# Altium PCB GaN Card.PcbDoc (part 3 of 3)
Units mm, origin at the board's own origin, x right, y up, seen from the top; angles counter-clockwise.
Board outline 50 x 40 mm, 6 copper layers (Top Layer, MidLayer1, MidLayer2, MidLayer3, MidLayer4, Bottom Layer), stack 1.981 mm thick; 88 components, 77 nets, 322 pads, 257 vias.
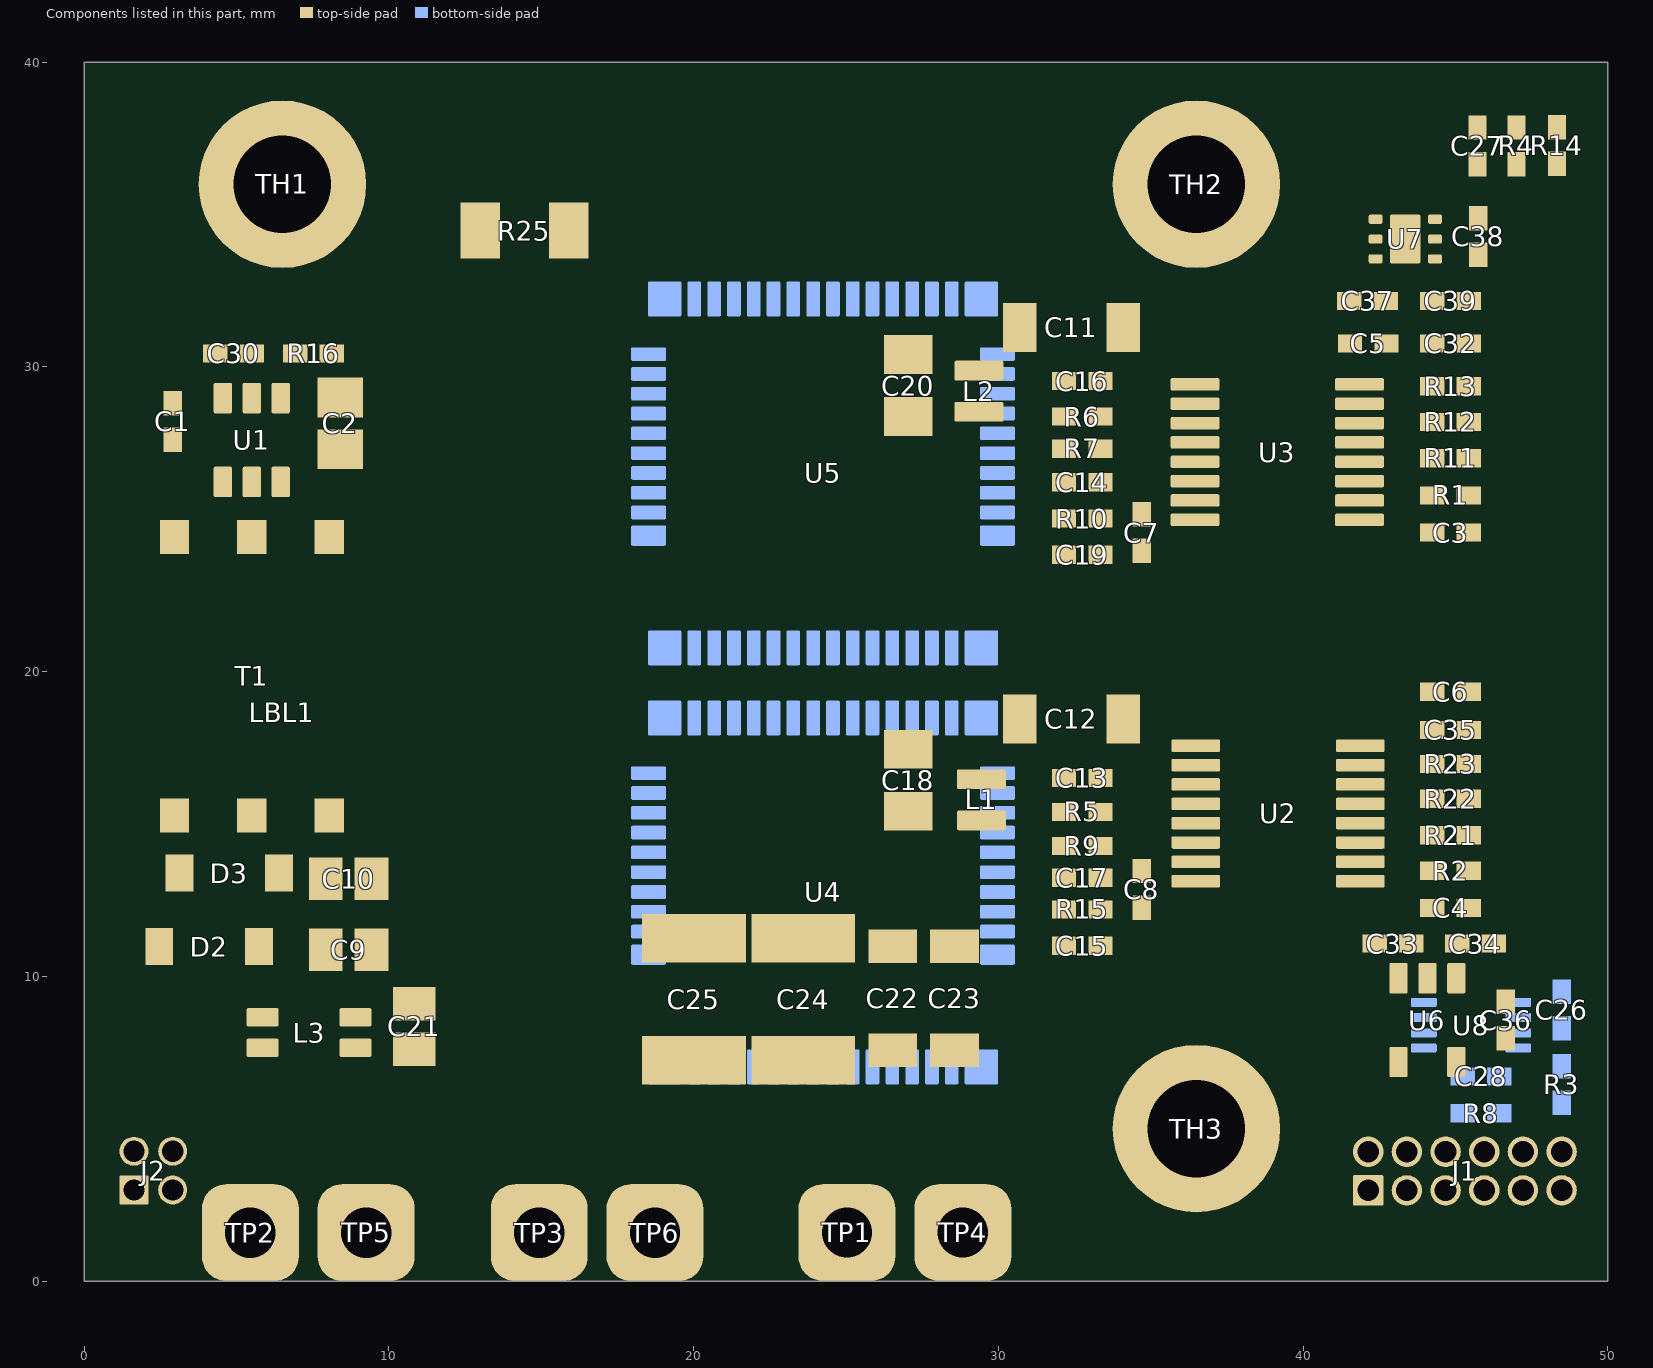
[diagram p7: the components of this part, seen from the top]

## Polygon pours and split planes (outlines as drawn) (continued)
SW on MidLayer2 "MidLayer1-SW" (solid, pour order 532): 29.353,18.554 29.268,18.639 29.268,21.012 30.406,22.15 36.288,22.15 36.844,21.593 37.454,20.984 37.454,11.342 36.326,10.214 28.411,10.214 27.421,11.205 27.421,16.547
PGND on MidLayer2 "MIDLAYER2_PGND_P528" (solid, pour order 528): 21.194,10.428 21.096,10.526 21.096,11.6 21.321,11.825 21.352,11.794 25.929,11.794 26.096,11.628 26.096,10.504 26.02,10.428
PGND on MidLayer2 "MIDLAYER2_PGND_P511" (solid, remove dead copper, pour order 511): 11.995,25.558 8.687,22.25 2.35,22.25 0.56,20.46 0.56,5.761 1.321,5 3.229,5 3.66,4.569 3.66,0.463 4.123,0 11.611,0 11.85,0.239 11.85,15.877 19.073,23.1 25.7,23.1 26.595,23.995 26.595,33.294 25.588,34.3 16.181,34.301 11.995,30.114
SW on MidLayer2 "MidLayer3-SW 1" (solid, pour order 518): 20.657,12.81 25.89,12.81 26.786,13.707 26.786,17.493 27.101,17.712 28.415,19.026 28.415,21.525 27.581,22.25 19.129,22.25 12.76,15.881 12.76,0.23 19.805,0.23 19.805,11.958
PGND on MidLayer2 "MidLayer1-PGND" (solid, pour order 513): 27.421,32.396 28.675,33.65 35.798,33.65 37.454,31.994 37.454,24.574 36.43,23.55 29.909,23.55 27.421,26.038
5V0 on MidLayer2 "MidLayer2-5V0" (solid, remove dead copper, pour order 502): 15.538,35.326 10.199,29.987 10.212,26.377 7.637,23.803 3.132,23.803 0.56,26.336 0.56,38.61 1.65,39.7 49.2,39.7 50,38.9 50,0.5 40.4,0.5 40.4,32.053 37.126,35.326
HVBUS on MidLayer2 "MidLayer4-PGND" (solid, pour order 469): 20.32,7.914 20.588,8.182 20.603,8.182 30.324,8.182 30.764,7.742 30.764,0.234 24.176,0.234 20.32,4.09
PGND on MidLayer1 "MidLayer1-PGND" (solid, pour order 418): 27.421,32.396 28.675,33.65 35.798,33.65 37.454,31.994 37.454,24.574 36.43,23.55 28.97,23.55 27.421,25.099
DGND on MidLayer1 "MidLayer1-DGND" (solid, remove dead copper, pour order 503): 49.754,39.153 49.2,39.707 1.65,39.7 0.56,38.61 0.56,26.336 3.132,23.803 7.637,23.803 10.208,26.374 10.208,29.995 15.538,35.326 35.842,35.326 37.126,35.326 40.4,32.053 40.4,0.246 49.754,0.246
PGND on MidLayer1 "MIDLAYER1_PGND_P519" (solid, remove dead copper, pour order 519): 11.995,25.558 8.687,22.25 2.35,22.25 0.56,20.46 0.56,5.761 1.321,5 3.229,5 3.66,4.569 3.66,0.463 4.123,0 11.611,0 11.85,0.239 11.85,16.018 18.932,23.1 25.7,23.1 26.595,23.995 26.595,33.294 25.588,34.3 16.181,34.301 11.995,30.114
HVBUS on MidLayer1 "MidLayer4-PGND" (solid, pour order 468): 19.997,7.591 20.588,8.182 20.603,8.182 30.324,8.182 30.764,7.742 30.764,0.246 24.164,0.246 19.997,4.413
PGND on MidLayer1 "MIDLAYER1_PGND_P526" (solid, pour order 526): 21.194,10.428 21.096,10.526 21.096,11.6 21.321,11.825 21.352,11.794 25.929,11.794 26.096,11.628 26.096,10.504 26.02,10.428
SW on MidLayer1 "MidLayer3-SW 1" (solid, pour order 520): 20.657,12.81 25.89,12.81 26.786,13.707 26.786,17.493 27.101,17.712 28.415,19.026 28.415,21.525 27.581,22.25 19.129,22.25 12.76,15.881 12.76,0.23 19.805,0.23 19.805,11.958
SW on MidLayer1 "MidLayer1-SW" (solid, pour order 420): 29.353,18.554 29.268,18.639 29.268,21.012 30.406,22.15 36.288,22.15 36.844,21.593 37.454,20.984 37.454,11.342 36.326,10.214 28.411,10.214 27.421,11.205 27.421,16.547
SW on MidLayer3 "MIDLAYER3_SW_P539" (solid, pour order 539): 19.431,16.798 25.003,16.798 25.003,19.001 25.682,19.679 27.845,19.679 28.31,20.144 28.31,21.637 27.951,21.995 19.782,21.995 19.377,21.591
SW on MidLayer3 "MidLayer1-SW" (solid, pour order 533): 29.268,18.466 29.268,21.012 30.406,22.15 36.288,22.15 36.844,21.593 37.454,20.984 37.454,11.342 36.326,10.214 28.411,10.214 27.421,11.205 27.421,16.547
PGND on MidLayer3 "MIDLAYER3_PGND_P530" (solid, pour order 530): 21.194,10.428 21.096,10.526 21.096,11.6 21.321,11.825 21.352,11.794 25.929,11.794 26.096,11.628 26.096,10.504 26.02,10.428
SW on MidLayer3 "MidLayer3-SW 1" (solid, pour order 522): 19.805,11.958 19.805,15.32 19.501,15.624 16.411,15.624 12.76,12.023 12.76,0.23 19.805,0.23
PGND on MidLayer3 "MIDLAYER3_PGND_P521" (solid, pour order 521): 15.249,16.158 19.874,16.158 20.379,15.653 20.379,11.157 21.004,10.532 26.05,10.532 26.595,11.077 26.595,24.493 26.595,32.38 25.191,33.784 16.234,33.784 11.995,29.545 11.995,25.558 8.687,22.25 2.35,22.25 0.56,20.46 0.56,5.761 1.321,5 3.229,5 3.66,4.569 3.66,0.463 4.123,0 11.611,0 11.995,0.384 11.995,12.904
PGND on MidLayer3 "MidLayer1-PGND" (solid, remove dead copper, pour order 515): 27.421,32.396 28.675,33.65 35.798,33.65 37.454,31.994 37.454,24.574 36.43,23.55 28.995,23.55 27.421,25.125
3V3 on MidLayer3 "MidLayer3-3V3" (solid, pour order 505): 15.538,35.326 10.199,29.987 10.212,26.377 7.637,23.803 4.053,23.803 0.56,27.243 0.56,38.61 1.65,39.7 49.2,39.7 50,38.9 50,0.5 40.4,0.5 40.4,32.053 37.126,35.326
HVBUS on MidLayer3 "MidLayer4-PGND" (solid, pour order 470): 20.32,7.914 20.588,8.182 30.324,8.182 30.764,7.742 30.764,0.234 24.176,0.234 20.32,4.09

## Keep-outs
Keep-Out Layer:
  lines w0.178: 32,-0.006 32.006,0 ; 45,40 0,40 0,0 19,0 30,-0.006 50,0 50,40
  text ".Layer_Name" at -16.126,-55.229 h0.6

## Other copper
Top Layer:
  pour cut-out: 46.209,34.237 46.277,34.305 46.277,35.503 45.236,35.503 45.241,35.498 45.241,34.3 45.457,34.084
  pour cut-out: 45.274,38.412 48.787,38.412 48.787,37.222 48.787,36.118 46.563,36.118 46.553,36.108 46.543,36.118 45.141,36.118 45.141,38.279
  region net NetC20_1: 28.526,31.042 28.686,31.203 28.686,31.364 28.5,31.55 26.58,31.55 26.24,31.209 26.24,30.02 27.84,30.407 27.84,30.862 28.02,31.042

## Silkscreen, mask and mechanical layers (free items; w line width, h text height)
Top Overlay:
  lines w0.254: 29.493,20.247 29.493,20.755
  text "GaN Card" at 17.989,36.759 h1.52
  text "PMP41126B" at 17.9,33.94 h1.52
  text "SW" at 16.112,3.982 h0.71
  text "HV-" at 6.917,3.909 h0.71
  text "HV+" at 25.868,3.909 h0.71
  text ".Layer_Name" at -16.126,-55.229 h0.6
Bottom Overlay:
  text "not FCC approved for resale." at 31.63,34.295 h0.71
  text ".Layer_Name" at -16.126,-55.229 h0.6
Top Paste:
  text ".Layer_Name" at -16.126,-55.229 h0.6
Bottom Paste:
  text ".Layer_Name" at -16.126,-55.229 h0.6
Top Solder:
  text ".Layer_Name" at -16.126,-55.229 h0.6
  text ".Layer_Name" at -16.126,-55.229 h0.6
Bottom Solder:
  text ".Layer_Name" at -16.126,-55.229 h0.6
Drill Guide:
  text ".Layer_Name" at -16.126,-55.229 h0.6
M1 Board Outline:
  lines w0.178: 0,0 0,40 50,40 50,0 24,0 10,0 0,0
  text ".Layer_Name" at -16.126,-55.229 h0.6
M2 Board Dimensions:
  circle w0.254: c36.5,5 r1.6
  circle w0.254: c6.5,36 r1.6
  rectangle: -30.781,-40.408 -27.606,-37.233
  rectangle: -27.606,-43.583 -18.081,-40.408
  lines w0.178: -30.781,-40.408 -5.381,-40.408 ; -27.606,-43.583 -27.606,-37.233 ; -24.431,-43.583 -24.431,-37.233 ; -18.081,-43.583 -18.081,-37.233 ; -11.731,-43.583 -11.731,-37.233 ; -30.781,-43.583 -5.381,-43.583 -5.381,-37.233 -30.781,-37.233 -30.781,-43.583
  text ".Layer_Name" at -16.126,-55.229 h0.6
M3 3D STEP Top:
  text ".Layer_Name" at -16.126,-55.229 h0.6
M4 3D STEP Bottom:
  text ".Layer_Name" at -16.126,-55.229 h0.6
M5 Assembly Top:
  lines w0.254: -38.198,-57.049 129.442,-57.049 ; -38.198,-51.885 129.493,-51.885 ; -38.198,-46.72 -38.198,-62.214 63.529,-62.214 129.493,-62.214 129.493,-46.72 -38.185,-46.72 -38.185,-62.214 1.832,-62.214 ; 24.413,-62.214 24.413,-46.72 ; 56.595,-51.885 56.595,-46.72 ; 77.931,-51.885 77.931,-46.72 ; 93.729,-62.379 93.729,-57.227
  text "COMPONENTS MARKED 'DNP' SHOULD NOT BE POPULATED." at -1.482,-41.513 h0.6
  text "ASSEMBLY VARIANT:" at -1.495,-44.447 h0.6
  text ".VariantName" at 24.819,-44.447 h0.6
  text "PCB VIEWED FROM TOP SIDE" at -36.585,-50.077 h0.6
  text "BOARD #:" at 26.318,-50.077 h0.6
  text ".PRJ_Number" at 40.174,-50.077 h0.6
  text "REV:" at 61.624,-50.077 h0.6
  text ".PCB_Rev" at 69.028,-50.077 h0.6
  text "SVN REV:" at 82.909,-50.077 h0.6
  text ".VersionControl_RevNumber" at 95.761,-50.077 h0.6
  text "TID #:" at 26.318,-55.242 h0.6
  text ".TID" at 40.174,-55.242 h0.6
  text "PLOT NAME =" at -36.585,-60.457 h0.6
  text ".plot_File_Name" at -16.126,-60.457 h0.6
  text "GENERATED    :" at 26.369,-60.457 h0.6
  text ".Print_Date" at 48.454,-60.457 h0.6
  text ".Print_Time" at 66.971,-60.457 h0.6
  text "TEXAS INSTRUMENTS" at 99.089,-60.457 h0.6
M6 Assembly Bottom:
  lines w0.254: -38.211,-51.897 129.48,-51.897 ; -38.16,-57.062 129.48,-57.062 ; -2.448,-62.392 -2.448,-57.24 ; 13.351,-51.897 13.351,-46.733 ; 34.687,-51.897 34.687,-46.733 ; 66.869,-62.227 66.869,-46.733 ; 89.45,-62.227 129.467,-62.227 129.467,-46.733 -38.211,-46.733 -38.211,-62.227 27.753,-62.227 129.48,-62.227 129.48,-46.733
  text "COMPONENTS MARKED 'DNP' SHOULD NOT BE POPULATED." at 124.209,-41.5 h0.6
  text ".VariantName" at 97.692,-44.447 h0.6
  text "ASSEMBLY VARIANT:" at 124.082,-44.447 h0.6
  text ".VersionControl_RevNumber" at -4.48,-50.09 h0.6
  text "SVN REV:" at 8.373,-50.09 h0.6
  text ".PCB_Rev" at 22.254,-50.09 h0.6
  text "REV:" at 29.658,-50.09 h0.6
  text ".PRJ_Number" at 51.108,-50.09 h0.6
  text "BOARD #:" at 64.964,-50.09 h0.6
  text "PCB VIEWED FROM BOTTOM SIDE" at 127.867,-50.09 h0.6
  text ".TID" at 51.108,-55.254 h0.6
  text "TID #:" at 64.964,-55.254 h0.6
  text "TEXAS INSTRUMENTS" at -7.807,-60.47 h0.6
  text ".Print_Time" at 24.311,-60.47 h0.6
  text ".Print_Date" at 42.828,-60.47 h0.6
  text "GENERATED    :" at 64.913,-60.47 h0.6
  text ".plot_File_Name" at 107.407,-60.47 h0.6
  text "PLOT NAME =" at 127.867,-60.47 h0.6
M9 Title Sheet:
  drawing of 57 lines, arcs and shapes, not listed
  text "1" at -11.989,170.704 h1.78
  text "2" at 51.4,170.704 h1.78
  text "3" at 114.63,170.704 h1.78
  text "4" at 178.299,170.704 h1.78
  text "5" at 241.773,170.704 h1.78
  text "6" at 305.4,170.704 h1.78
  text "A" at -41.36,141.672 h1.78
  text "A" at 334.56,141.672 h1.78
  text "B" at -41.36,81.22 h1.78
  text "B" at 334.56,81.22 h1.78
  text "C" at -41.36,20.895 h1.78
  text "C" at 334.56,20.895 h1.78
  text "PROJECT TITLE:" at 257.344,-26.375 h1.14
  text ".PRJ_Title" at 258.614,-29.761 h1.78
  text "DESIGNED FOR:" at 257.344,-34.02 h1.14
  text ".PRJ_Customer" at 258.614,-37.576 h1.78
  text "D" at -41.36,-39.303 h1.78
  text "D" at 334.56,-39.303 h1.78
  text "FILE NAME:" at 257.344,-41.64 h1.14
  text ".PCB_File_Name_No_Path" at 258.614,-44.688 h1.78
  text "Texas Instruments (TI) and/or its licensors do not warrant the accuracy or completeness of this specification" at 131.118,-48.799 h1.14
  text "ENGINEER:" at 257.344,-49.006 h1.14
  text "LAYOUT BY:" at 295.571,-49.006 h1.14
  text "or any information contained therein. TI and/or its licensors do not warrant that this design will meet" at 129.976,-51.66 h1.14
  text ".PRJ_Engineer" at 258.614,-52.943 h1.78
  text ".PCB_Layout" at 296.853,-52.943 h1.78
  text "the specifications, will be suitable for your application or fit for any particular purpose, or will operate in" at 129.976,-54.522 h1.14
  text ".Layer_Name" at -16.126,-55.229 h0.6
  text "ALTIUM DESIGNER VERSION:" at 295.571,-56.88 h1.14
  text "an implementation. TI and/or its licensors do not warrant that the design is production worthy. You should" at 129.976,-57.384 h1.14
  text "completely validate and test your design implementation to confirm the system functionality for your application." at 131.118,-60.245 h1.14
  text ".print_Scale" at 258.614,-60.267 h1.78
  text ".Application_BuildNumber" at 296.853,-60.267 h1.78
  text "1" at -11.989,-65.516 h1.78
  text "2" at 51.4,-65.516 h1.78
  text "3" at 114.63,-65.516 h1.78
  text "4" at 178.299,-65.516 h1.78
  text "5" at 241.773,-65.516 h1.78
  text "6" at 305.4,-65.516 h1.78
M10 Fab Notes:
  drawing of 189 lines, arcs and shapes, not listed
  text "DESIGN INFORMATION" at 283.722,128.024 h0.6
  text "MIN. TRACK WIDTH:" at 267.35,124.668 h0.6
  text "8" at 295.195,124.668 h0.6
  text "MIL" at 299.126,124.668 h0.6
  text "MIN. CLEARANCE:" at 267.35,121.515 h0.6
  text "0.2" at 293.671,121.515 h0.6
  text "mm" at 299.126,121.515 h0.6
  text "MIN. VIA PAD SIZE:" at 267.35,118.362 h0.6
  text "24" at 294.433,118.362 h0.6
  text "MIL" at 299.126,118.362 h0.6
  text "0.05mm (2MIL)" at 285.003,115.063 h0.6
  text "MINIMUM ANNULAR RING" at 258.988,114.854 h0.6
  text "EXTERNAL" at 302.986,114.854 h0.6
  text "PER" at 264.068,112.057 h0.6
  text "IPC-D-275 CLASS 2 LEVEL C" at 269.656,112.057 h0.6
  text "MIL, HOLES" at 307.457,109.504 h0.6
  text "+/-" at 297.488,109.286 h0.6
  text "+/-" at 319.18,109.286 h0.6
  text "REGISTRATION TOLERANCES:" at 258.988,109.259 h0.6
  text "METAL" at 289.462,109.259 h0.6
  text "5" at 304.097,109.259 h0.6
  text "3" at 325.256,109.259 h0.6
  text "MIL" at 328.209,109.259 h0.6
  text "HOLE SIZE TOLERANCE (UNLESS OTHERWISE SPECIFIED):" at 258.988,106.762 h0.6
  text "+/-" at 319.18,106.689 h0.6
  text "3" at 325.256,106.662 h0.6
  text "MIL" at 328.209,106.662 h0.6
  text "MATERIAL:" at 257.089,103.166 h0.6
  text "FR-4 High Tg" at 282.144,99.901 h0.6
  text "X" at 278.475,99.698 h0.6
  text "FR-408" at 267.782,99.584 h0.6
  text "OTHER" at 305.577,99.584 h0.6
  text "62 MIL (1.6mm) +/-10%" at 275.913,95.951 h0.6
  text "X" at 272.862,95.888 h0.6
  text "THICKNESS:" at 258.988,95.742 h0.6
  text "OTHER" at 308.549,95.742 h0.6
  text "TOLERANCE:" at 258.988,92.229 h0.6
  text "X" at 280.533,92.229 h0.6
  text "ANSI IPC-6012 TYPE 3 CLASS 2" at 285.054,92.229 h0.6
  text "OTHER +/-" at 285.054,88.566 h0.6
  text "BOW & TWIST:" at 258.988,84.879 h0.6
  text "X" at 280.533,84.879 h0.6
  text "ANSI IPC-6012 TYPE 3 CLASS 2" at 285.054,84.879 h0.6
  text "OTHER +/-" at 285.054,81.152 h0.6
  text "DRILLING:" at 257.089,77.835 h0.6
  text "NC_DRILL FILES" at 301.818,75.163 h0.6
  text "REFERENCE:" at 258.988,75.063 h0.6
  text "X" at 275.681,75.06 h0.6
  text "AS SHOWN" at 280.203,75.063 h0.6
  text "X" at 298.567,75.063 h0.6
  text "OTHER" at 309.387,71.45 h0.6
  text "PTH COPPER THICKNESS:" at 258.979,71.36 h0.6
  text "X" at 287.916,71.36 h0.6
  text "20-30 um" at 291.167,71.36 h0.6
  text "BOARD FINISH:" at 257.089,67.611 h0.6
  text "SILKSCREEN:" at 261.031,64.814 h0.6
  text "X" at 285.359,64.814 h0.6
  text "TOP" at 288.331,64.814 h0.6
  text "X" at 298.313,64.814 h0.6
  text "BOTTOM" at 301.31,64.814 h0.6
  text "SILKSCREEN COLOR:" at 261.031,60.872 h0.6
  text "X" at 285.333,60.872 h0.6
  text "WHITE" at 288.331,60.872 h0.6
  text "OTHER" at 301.31,60.872 h0.6
  text "X" at 288.661,57.229 h0.6
  text "GREEN" at 291.658,57.229 h0.6
  text "OTHER" at 307.355,57.229 h0.6
  text "SOLDER RESIST COLOR:" at 261.031,57.054 h0.6
  text "X" at 288.661,53.311 h0.6
  text "MATTE" at 291.658,53.311 h0.6
  text "SEMI-GLOSS" at 307.343,53.294 h0.6
  text "IMMERSION GOLD (ENIG)" at 284.038,48.922 h0.6
  text "ENEPIG" at 318.011,48.739 h0.6
  text "SURFACE FINISH:" at 257.089,48.713 h0.6
  text "X" at 279.517,48.713 h0.6
  text "IMM. TIN/SILVER OR EQUIV" at 265.459,45.226 h0.6
  text "OTHER" at 301.818,45.126 h0.6
  text "ARRAY/PANEL:" at 257.089,41.179 h0.6
  text "CUT AND TRIM PER M1 BOARD OUTLINE" at 284.038,40.97 h0.6
  text "N.C. ROUTE" at 284.038,37.517 h0.6
  text "X" at 301.513,37.517 h0.6
  text "V. SCORE" at 306.034,37.517 h0.6
  text "CERTIFICATION:" at 257.089,34.237 h0.6
  text "MATERIALS AND WORKMANSHIP FOR ALL PCBS" at 275.504,34.237 h0.6
  text "TO MEET OR EXCEED THE REQUIREMENTS OF:" at 275.504,31.848 h0.6
  text "X" at 266.296,28.58 h0.6
  text "ANSI IPC-A-600F CLASS ->" at 269.547,28.58 h0.6
  text "X" at 311.407,28.58 h0.6
  text "2" at 314.201,28.58 h0.6
  text "1" at 306.2,28.542 h0.6
  text "3" at 323.192,28.542 h0.6
  text "X" at 286.921,24.829 h0.6
  text "RoHS" at 290.172,24.829 h0.6
  text "OTHER" at 306.54,24.829 h0.6
  text "PER ORDER" at 316.625,24.829 h0.6
  text "ALL BOARDS MUST MEET OR EXCEED UL94-V0 REQUIREMENTS." at 257.788,20.922 h0.6
  text "PCB MUST BEAR THE UL94V-0 UL REGISTERED MATERIAL ID NUMBER" at 257.788,17.974 h0.6
  text "ADDITIONAL REQUIREMENTS:" at 257.089,13.671 h0.6
  text "MICROSECTION:" at 258.988,10.95 h0.6
  text "YES" at 281.993,10.95 h0.6
  text "REQUIRED" at 303.875,7.283 h0.6
  text "BARE BOARD ELEC. TEST:" at 258.988,7.211 h0.6
  text "NONE" at 292.153,7.211 h0.6
  text "X" at 300.878,7.211 h0.6
  text "PER ORDER" at 318.912,7.211 h0.6
  text "XX MIL VIAS REQUIRE NON-CONDUCTIVE FILL AND PLANARIZE" at 263.259,2.005 h1.5
  text "XX MIL VIAS REQUIRE CONDUCTIVE FILL AND PLANARIZE" at 263.462,-0.636 h0.6
  text "OUTER XX MIL TRACES REQUIRE 50 OHM SINGLE-ENDED IMPEDANCE" at 263.437,-4.786 h1.47
  text "LAYER 2 & 3 (INNER LAYERS) XX MIL WIDE, XX MIL SPACE / TRACES REQUIRE 100 OHM DIFFERENTIAL IMPEDANCE" at 263.234,-10.773 h0.6
  text ".Layer_Name" at -16.126,-55.229 h0.6
M11 Gerber Information:
  lines w0.254: -38.198,-57.049 129.442,-57.049 ; -38.198,-51.885 129.493,-51.885 ; -38.198,-46.72 -38.198,-62.214 63.529,-62.214 129.493,-62.214 129.493,-46.72 -38.185,-46.72 -38.185,-62.214 1.832,-62.214 ; 24.413,-62.214 24.413,-46.72 ; 56.595,-51.885 56.595,-46.72 ; 77.931,-51.885 77.931,-46.72 ; 93.729,-62.379 93.729,-57.227
  text "ALL ARTWORK VIEWED FROM TOP SIDE" at -36.585,-50.077 h0.6
  text "BOARD #:" at 26.318,-50.077 h0.6
  text ".PRJ_Number" at 40.174,-50.077 h0.6
  text "REV:" at 61.624,-50.077 h0.6
  text ".PCB_Rev" at 69.028,-50.077 h0.6
  text "SVN REV:" at 82.909,-50.077 h0.6
  text ".VersionControl_RevNumber" at 95.761,-50.077 h0.6
  text "LAYER NAME =" at -36.585,-55.229 h0.6
  text "TID #:" at 26.318,-55.242 h0.6
  text ".TID" at 40.174,-55.242 h0.6
  text "PLOT NAME =" at -36.585,-60.457 h0.6
  text ".plot_File_Name" at -16.126,-60.457 h0.6
  text "GENERATED    :" at 26.369,-60.457 h0.6
  text ".Print_Date" at 48.454,-60.457 h0.6
  text ".Print_Time" at 66.971,-60.457 h0.6
  text "TEXAS INSTRUMENTS" at 99.089,-60.457 h0.6
M12 Stackup:
  drawing of 7763 lines, arcs and shapes, not listed
  text "Layer" at 217.414,166.273 h0.6
  text "Name" at 221.821,166.273 h0.6
  text "Material" at 231.426,166.273 h0.6
  text "Thickness" at 240.332,166.273 h0.6
  text "Constant" at 247.138,166.273 h0.6
  text "Board Layer Stack" at 253.145,166.273 h0.6
  text "Board Layer Stack" at 264.65,166.273 h0.6
  text "Board Layer Stack" at 276.155,166.273 h0.6
  text "Board Layer Stack" at 287.66,166.273 h0.6
  text "Board Layer Stack" at 299.164,166.273 h0.6
  text "Board Layer Stack" at 310.669,166.273 h0.6
  text "Board Layer Stack" at 322.174,166.273 h0.6
  text "Board Layer Stack" at 333.679,166.273 h0.6
  text "Board Layer Stack" at 345.184,166.273 h0.6
  text "Board Layer Stack" at 356.688,166.273 h0.6
  text "Board Layer Stack" at 368.193,166.273 h0.6
  text "Board Layer Stack" at 379.698,166.273 h0.6
  text "Board Layer Stack" at 391.203,166.273 h0.6
  text "Board Layer Stack" at 402.708,166.273 h0.6
  text "Board Layer Stack" at 414.213,166.273 h0.6
  text "Top Overlay" at 221.821,165.073 h0.6
  text "Top Solder" at 221.821,163.873 h0.6
  text "Solder Resist" at 231.426,163.873 h0.6
  text "0.40mil" at 240.332,163.873 h0.6
  text "3.5" at 247.138,163.873 h0.6
  text "1" at 217.414,162.673 h0.6
  text "Top Layer" at 221.821,162.673 h0.6
  text "2.80mil" at 240.332,162.673 h0.6
  text "Dielectric 1" at 221.821,161.473 h0.6
  text "FR-4 High Tg" at 231.426,161.473 h0.6
  text "4.60mil" at 240.332,161.473 h0.6
  text "4.2" at 247.138,161.473 h0.6
  text "2" at 217.414,160.273 h0.6
  text "MidLayer1" at 221.821,160.273 h0.6
  text "2.80mil" at 240.332,160.273 h0.6
  text "Dielectric 2" at 221.821,159.073 h0.6
  text "FR-4 High Tg" at 231.426,159.073 h0.6
  text "23.70mil" at 240.332,159.073 h0.6
  text "4.2" at 247.138,159.073 h0.6
  text "3" at 217.414,157.873 h0.6
  text "MidLayer2" at 221.821,157.873 h0.6
  text "2.80mil" at 240.332,157.873 h0.6
  text "4.6" at 221.821,156.673 h0.6
  text "FR-4 High Tg" at 231.426,156.673 h0.6
  text "4.60mil" at 240.332,156.673 h0.6
  text "4.2" at 247.138,156.673 h0.6
  text "4" at 217.414,155.473 h0.6
  text "MidLayer3" at 221.821,155.473 h0.6
  text "2.80mil" at 240.332,155.473 h0.6
  text "Dielectric 4" at 221.821,154.273 h0.6
  text "23.70mil" at 240.332,154.273 h0.6
  text "4.2" at 247.138,154.273 h0.6
  text "5" at 217.414,153.073 h0.6
  text "MidLayer4" at 221.821,153.073 h0.6
  text "2.80mil" at 240.332,153.073 h0.6
  text "Dielectric 5" at 221.821,151.873 h0.6
  text "4.60mil" at 240.332,151.873 h0.6
  text "4.2" at 247.138,151.873 h0.6
  text "6" at 217.414,150.673 h0.6
  text "Bottom Layer" at 221.821,150.673 h0.6
  text "2.80mil" at 240.332,150.673 h0.6
  text "Bottom Solder" at 221.821,149.473 h0.6
  text "Solder Resist" at 231.426,149.473 h0.6
  text "0.40mil" at 240.332,149.473 h0.6
  text "3.5" at 247.138,149.473 h0.6
  text "Bottom Overlay" at 221.821,148.273 h0.6
  text ".Layer_Name" at -16.126,-55.229 h0.6
M13 Component Bodies Top:
  text ".Layer_Name" at -16.126,-55.229 h0.6
M14 Component Bodies Bottom:
  text ".Layer_Name" at -16.126,-55.229 h0.6
M15 Courtyards Top:
  text ".Layer_Name" at -16.126,-55.229 h0.6
M16 Courtyards Bottom:
  text ".Layer_Name" at -16.126,-55.229 h0.6
Drill Drawing:
  circle w0.254: c104.462,44.643 r0.333
  lines w0.254: 104.129,45.809 104.796,45.809 104.796,46.476 104.129,46.476 104.129,45.809 ; 104.129,47.309 104.462,47.476 104.796,47.309 104.629,47.643 104.796,47.976 104.462,47.809 104.129,47.976 104.296,47.643 104.129,47.309 ; 104.129,48.976 104.296,48.976 104.296,48.809 104.629,48.809 104.629,48.976 104.796,48.976 104.796,49.309 104.629,49.309 104.629,49.476 104.296,49.476 104.296,49.309 104.129,49.309 104.129,48.976 ; 104.129,50.976 104.796,50.976 104.462,50.309 104.129,50.976 ; 104.129,51.976 104.296,51.976 104.462,51.809 104.629,51.976 104.796,51.976 104.629,52.143 104.796,52.309 104.629,52.309 104.462,52.476 104.296,52.309 104.129,52.309 104.296,52.143 104.129,51.976
  lines w0.305: 103.483,43.859 170.75,43.859 ; 103.483,52.859 170.75,52.859 ; 109.485,42.359 109.485,54.359 ; 116.356,42.359 116.356,54.359 ; 130.305,42.359 130.305,54.359 ; 135.856,42.359 135.856,54.359 ; 143.687,42.359 143.687,54.359 ; 158.99,42.359 158.99,54.359 ; 103.483,42.359 170.75,42.359 170.75,54.359 103.483,54.359 103.483,42.359
  text "Symbol" at 104.383,53.309 h0.72
  text "Quantity" at 109.935,53.309 h0.72
  text "Finished Hole Size" at 116.806,53.309 h0.72
  text "Plated" at 130.755,53.309 h0.72
  text "Hole Type" at 136.306,53.309 h0.72
  text "Drill Layer Pair" at 144.137,53.309 h0.72
  text "Hole Tolerance" at 159.44,53.309 h0.72
  text "2" at 109.935,51.809 h0.6
  text "7.87mil (0.200mm)" at 116.806,51.809 h0.6
  text "PTH" at 130.755,51.809 h0.6
  text "Round" at 136.306,51.809 h0.6
  text "Top Layer - Bottom Layer" at 144.137,51.809 h0.6
  text "255" at 109.935,50.309 h0.6
  text "10.00mil (0.254mm)" at 116.806,50.309 h0.6
  text "PTH" at 130.755,50.309 h0.6
  text "Round" at 136.306,50.309 h0.6
  text "Top Layer - Bottom Layer" at 144.137,50.309 h0.6
  text "4" at 109.935,48.809 h0.6
  text "27.56mil (0.700mm)" at 116.806,48.809 h0.6
  text "PTH" at 130.755,48.809 h0.6
  text "Round" at 136.306,48.809 h0.6
  text "Top Layer - Bottom Layer" at 144.137,48.809 h0.6
  text "12" at 109.935,47.309 h0.6
  text "27.95mil (0.710mm)" at 116.806,47.309 h0.6
  text "PTH" at 130.755,47.309 h0.6
  text "Round" at 136.306,47.309 h0.6
  text "Top Layer - Bottom Layer" at 144.137,47.309 h0.6
  text "6" at 109.935,45.809 h0.6
  text "64.96mil (1.650mm)" at 116.806,45.809 h0.6
  text "PTH" at 130.755,45.809 h0.6
  text "Round" at 136.306,45.809 h0.6
  text "Top Layer - Bottom Layer" at 144.137,45.809 h0.6
  text "3" at 109.935,44.309 h0.6
  text "125.98mil (3.200mm)" at 116.806,44.309 h0.6
  text "PTH" at 130.755,44.309 h0.6
  text "Round" at 136.306,44.309 h0.6
  text "Top Layer - Bottom Layer" at 144.137,44.309 h0.6
  text "282 Total" at 109.935,42.809 h0.6
  text ".Layer_Name" at -16.126,-55.229 h0.6
M17 Embedded Cavity:
  text ".Layer_Name" at -16.126,-55.229 h0.6
M18 Embedded Assembly:
  text ".Layer_Name" at -16.126,-55.229 h0.6
M19 Embedded Keepout:
  text ".Layer_Name" at -16.126,-55.229 h0.6

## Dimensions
36.5,5 to 40,8.5 on M2 Board Dimensions
6.5,36 to 13.15,29.4 on M2 Board Dimensions
0,40 to 50,40 on M2 Board Dimensions
-30.781,-43.583 to -5.381,-43.583 on M2 Board Dimensions
0,40 to -0.25,0 on M2 Board Dimensions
